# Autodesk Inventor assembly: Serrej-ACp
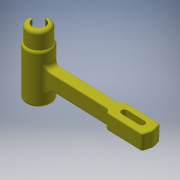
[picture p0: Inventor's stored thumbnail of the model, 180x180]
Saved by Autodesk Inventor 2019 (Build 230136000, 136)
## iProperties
Created: 2019-02
Part Number: Serrej-ACp
Material: Générique
Document SubType Name: Assembly
Designer: si-nd67
Author: si-nd67
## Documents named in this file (3)
- E:\ECAM\serrejointsw\Serrej-ACp.iam
- E:\ECAM\serrejointsw\Mors mobile14C.ipt
- E:\ECAM\serrejointsw\GoupilleElast112-14.ipt
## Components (2 placed, 2 different names)
1. Mors mobile14C:1 — Placage:1, Placage:2
2. GoupilleElast112-14:1 — Placage:1, Placage:2
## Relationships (2: Mate 2)
- Placage:1 [Mate]: Mors mobile14C:1 ↔ GoupilleElast112-14:1
- Placage:2 [Mate]: Mors mobile14C:1 ↔ GoupilleElast112-14:1
